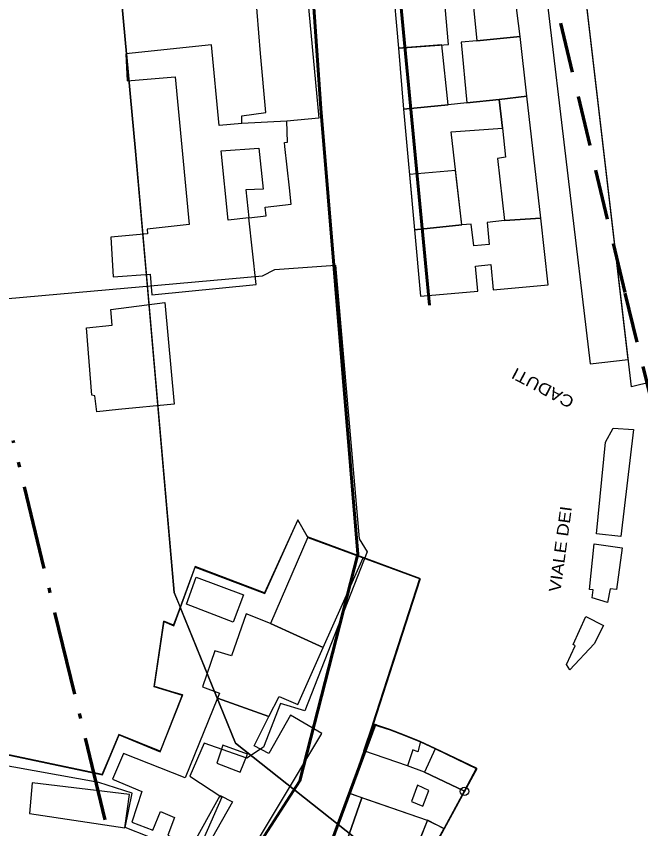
# Model space of a CAD drawing. Extents: x 654952 to 658955, y 890426 to 894481.
# Drawn here: x 658012.7 to 658161.5, y 891148.5 to 891342 of the extents above; entities that cross this region are included whole.
import ezdxf

# ---------------------------------------------------------------- set-up
doc = ezdxf.new("R2010")
doc.units = 0
doc.header["$LTSCALE"] = 4
doc.header["$PDMODE"] = 32
doc.header["$PDSIZE"] = 2
doc.linetypes.add('DOT_DASHED', pattern=[7.7, 5, -1.2, 0.3, -1.2])
doc.linetypes.add('MEDIUM_DASHED', pattern=[4.5, 3, -1.5])
for name, color, linetype, lineweight in [('1', 7, 'Continuous', 25), ('4', 7, 'Continuous', 25), ('40', 7, 'Continuous', 60), ('45', 7, 'Continuous', 25), ('55', 7, 'Continuous', 25), ('8', 7, 'Continuous', 25)]:
    doc.layers.add(name, color=color, linetype=linetype, lineweight=lineweight)
doc.layers.add('58', color=7, linetype='Continuous')

msp = doc.modelspace()

# ---------------------------------------------------------------- linework, layer by layer
at = {"layer": '1'}
for points in [[(658205.89, 891269.14), (658206.8, 891265.48), (658159.27, 891253.81), (658132.26, 891484.14), (658144.06, 891484.59)], [(658079.75, 891222.1), (658071.86, 891204.67), (658055.29, 891210.95), (658050.19, 891196.98), (658047.85, 891197.98), (658045.52, 891182.46)], [(658050.23, 891196.88), (658055.33, 891210.85), (658071.9, 891204.57), (658079.79, 891222), (658082.17, 891217.91), (658108.92, 891208.01)], [(658097.66, 891173.47), (658106.26, 891200.05), (658108.88, 891208.11), (658082.13, 891218.01), (658079.75, 891222.1)], [(658108.92, 891208.01), (658106.3, 891199.95), (658097.7, 891173.37), (658101.77, 891172.07), (658105.25, 891170.7), (658109.01, 891169.22), (658112.57, 891167.52), (658122.43, 891162.82), (658119.5, 891157.43)], [(658103.03, 891128.29), (658099.62, 891134.92), (658095.53, 891144.7), (658064.96, 891168.92), (658051.77, 891201.3), (658050.19, 891196.98), (658047.85, 891197.98), (658045.52, 891182.46)], [(658006.76, 891166.92), (658033.23, 891161.37), (658037.2, 891170.9), (658047.02, 891166.87), (658052.34, 891180.28), (658045.56, 891182.36), (658047.89, 891197.88), (658050.23, 891196.88)], [(658045.52, 891182.46), (658052.3, 891180.38), (658046.98, 891166.97), (658037.16, 891171), (658033.19, 891161.47), (658006.72, 891167.02), (658006.74, 891166.97), (658033.19, 891161.47), (658006.74, 891166.97)], [(658045.52, 891182.46), (658052.3, 891180.38), (658046.98, 891166.97), (658037.16, 891171), (658033.19, 891161.47), (658006.72, 891167.02), (658006.74, 891166.97)], [(658181.48, 891090.36), (658134.43, 891072.77), (658128.69, 891081.52), (658121.85, 891091.3), (658116.36, 891087.89), (658115.35, 891089.62), (658106.95, 891104.02), (658117.31, 891121.09), (658122.66, 891129.89), (658126.23, 891136.01), (658112.4, 891144.62), (658114.64, 891148.62), (658112.63, 891144.93), (658119.46, 891157.53), (658122.39, 891162.92), (658112.53, 891167.62), (658108.97, 891169.32), (658105.21, 891170.8), (658101.73, 891172.17), (658097.66, 891173.47)], [(658119.5, 891157.43), (658112.67, 891144.83), (658114.68, 891148.52), (658112.44, 891144.52), (658126.27, 891135.91), (658122.7, 891129.79), (658117.35, 891120.99), (658106.99, 891103.92), (658115.39, 891089.52), (658116.4, 891087.79), (658121.89, 891091.2), (658128.73, 891081.42), (658134.47, 891072.67), (658181.52, 891090.26), (658218.54, 891002.58), (658195.38, 890993.42), (658184.51, 891003.86), (658180.37, 891008.29), (658170.47, 891014.21), (658166.6, 891016.69), (658164.47, 891018.68), (658153.51, 891027.33), (658145.94, 891016.68), (658139.53, 891006.49)]]:
    msp.add_lwpolyline(points, dxfattribs=at)
msp.add_point((658119.5, 891157.43), dxfattribs=at)
at = {"layer": '4'}
for points in [[(658122.85, 891483.18), (658149.44, 891259.26), (658158.51, 891260.32), (658132.26, 891484.14)], [(658122.85, 891483.18), (658149.44, 891259.26), (658158.51, 891260.32), (658132.26, 891484.14)], [(658120.76, 891353.1), (658122.4, 891336.2), (658132.75, 891337.2), (658130.63, 891354.02)], [(658103.81, 891334.44), (658115.66, 891335.34), (658114.18, 891352.48), (658102.24, 891351.36)], [(658069.73, 891348), (658069.51, 891350.76), (658081.59, 891351.78), (658084.78, 891317.76), (658077.13, 891317.08), (658066.48, 891316.52), (658066.45, 891318.32), (658072.15, 891319.1), (658070.87, 891333.18)], [(658118.68, 891335.84), (658120.08, 891321.4), (658127.75, 891322.24), (658134.36, 891322.98), (658132.75, 891337.2), (658122.4, 891336.2)], [(658063.18, 891293.46), (658061.54, 891309.98), (658070.5, 891310.6), (658071.53, 891300.88), (658067.37, 891300.7), (658068.08, 891294), (658072.24, 891294.46), (658072.01, 891296.56), (658078.22, 891297.24), (658077.78, 891301.16), (658076.7, 891311), (658076.59, 891311.98), (658077.36, 891312.08), (658077.13, 891317.08), (658066.48, 891316.52), (658061.01, 891316.04), (658059.21, 891335.22), (658038.79, 891333.08), (658039.14, 891326.62), (658050.6, 891327.62), (658053.93, 891292.44), (658043.85, 891291.32), (658043.93, 891290.22), (658035.22, 891289.42), (658035.81, 891280), (658044.59, 891280.64), (658045.01, 891275.66), (658069.87, 891278.16), (658068.08, 891294)], [(658103.81, 891334.44), (658104.97, 891319.94), (658115.64, 891320.94), (658114.09, 891335.22)], [(658127.75, 891322.24), (658128.52, 891315.4), (658129.29, 891308.5), (658127.39, 891308.16), (658129.04, 891293.4), (658137.66, 891293.96), (658134.36, 891322.98)], [(658104.97, 891319.94), (658107.58, 891291.2), (658118.86, 891292.38), (658116.35, 891314.54), (658128.52, 891315.4), (658127.75, 891322.24), (658120.08, 891321.4), (658115.64, 891320.94)], [(658106.38, 891304.38), (658107.58, 891291.2), (658118.86, 891292.38), (658117.39, 891305.26)], [(658107.58, 891291.2), (658109.02, 891275.34), (658122.64, 891276.56), (658122.1, 891282.5), (658125.8, 891282.88), (658126.33, 891276.88), (658139.47, 891278.06), (658137.66, 891293.96), (658129.04, 891293.4), (658124.92, 891292.94), (658125.38, 891287.7), (658121.74, 891287.34), (658121.09, 891292.52), (658118.86, 891292.38)], [(658030.73, 891251.82), (658029.44, 891267.82), (658035.56, 891268.48), (658035.24, 891272.22), (658048.1, 891273.82), (658050.3, 891249.62), (658037.06, 891248.34), (658031.86, 891247.78), (658031.43, 891251.64)], [(658159.77, 891243.62), (658156.77, 891218.14), (658150.96, 891218.78), (658153.13, 891240.62), (658154.9, 891243.94)], [(658073.24, 891197.42), (658085.84, 891191.68), (658095.37, 891213.08), (658082.15, 891217.96)], [(658150.42, 891216.36), (658157.03, 891215.44), (658155.75, 891205.5), (658154.21, 891205.68), (658153.56, 891202.4), (658149.88, 891203.5), (658150.18, 891205.42), (658149.27, 891205.54)], [(658053.25, 891202), (658055.56, 891208.44), (658066.81, 891204.22), (658064.38, 891197.74)], [(658057.07, 891182.34), (658061.13, 891180.8), (658060.65, 891179.62), (658072.91, 891175.24), (658075.33, 891180.02), (658079.78, 891178.08), (658085.84, 891191.68), (658073.24, 891197.42), (658067.44, 891199.7), (658064.01, 891189.68), (658060, 891190.92)], [(658152.63, 891196.94), (658150.39, 891192.54), (658144.56, 891186.36), (658143.81, 891187.66), (658145.86, 891192.08), (658145.4, 891192.44), (658148.41, 891199.04)], [(658060.65, 891179.62), (658052.96, 891160.66), (658038.23, 891166.46), (658035.63, 891160.34), (658042.58, 891157.4), (658040.22, 891150.1), (658045.26, 891148.22), (658047.04, 891152.62), (658050.44, 891151.18), (658048.84, 891147), (658054.43, 891144.14), (658061.32, 891156.46), (658064.23, 891154.96), (658056.73, 891141.74), (658065.07, 891137.18), (658085.54, 891171.24), (658078.05, 891175.56), (658072.91, 891166.42), (658069.35, 891168.24), (658072.91, 891175.24)], [(658108.99, 891169.28), (658108.42, 891166.84), (658107.21, 891167.32), (658105.91, 891163.5), (658095.5, 891167.1), (658097.68, 891173.42), (658101.75, 891172.12)], [(658061.94, 891168.42), (658060.45, 891164.14), (658066.04, 891162), (658067.79, 891166.26)], [(658092.02, 891157.02), (658110.63, 891150.56), (658114.66, 891148.58), (658119.49, 891157.48), (658109.96, 891162.02), (658105.91, 891163.5), (658095.5, 891167.1)], [(658112.55, 891167.58), (658109.96, 891162.02), (658119.49, 891157.48), (658122.41, 891162.88)], [(658016.45, 891159.48), (658015.85, 891152.14), (658038.56, 891148.72), (658039.65, 891156.64)], [(658108.3, 891158.88), (658106.85, 891154.98), (658109.6, 891153.9), (658110.98, 891157.66)], [(658095.06, 891155.92), (658092.04, 891156.97), (658083.37, 891132.7), (658086.52, 891131.53)], [(658095.06, 891155.92), (658086.52, 891131.53), (658095.23, 891128.41), (658098, 891135.1), (658102.74, 891133.01), (658107.11, 891146.12), (658108.72, 891145.59), (658110.65, 891150.5)], [(658110.67, 891150.54), (658108.72, 891145.59), (658107.11, 891146.12), (658102.74, 891133.01), (658098, 891135.1), (658095.23, 891128.41), (658099.18, 891127), (658100.99, 891130.66), (658104, 891129.44), (658105.41, 891131.62), (658112.4, 891144.62), (658114.68, 891148.52)]]:
    msp.add_lwpolyline(points, close=True, dxfattribs=at)
at = {"layer": '40'}
for points in [[(658111.19, 891273.19), (658100.58, 891384.08), (658092.91, 891475.8), (658084.96, 891556.9), (658074.93, 891576.95), (658031.01, 891631.21)], [(658047.53, 891586.68), (658065.8, 891564.56), (658072.58, 891488.48), (658078.76, 891414.16), (658085.24, 891320.08), (658094.09, 891213.92), (658080.24, 891159.95), (658043.39, 891102.74), (658023.06, 891083.86), (658008.02, 891082.68)], [(658011.86, 891072.95), (658031.31, 891075.31), (658056.36, 891086.22), (658072.57, 891104.21), (658098.22, 891173.51)]]:
    msp.add_lwpolyline(points, dxfattribs=at)
at = {"layer": '45', "linetype": 'MEDIUM_DASHED', "lineweight": 70}
for points in [[(658157.77, 891276.21), (658107.08, 891488.64), (658089.9, 891548.82), (658084.95, 891562.68), (658066.38, 891640.44), (658054.95, 891687.7), (658032.46, 891785.55), (658025.97, 891822.86), (658018.45, 891880.89), (658014.38, 891931.66), (658013.11, 891975.37), (658014.47, 892047.73), (658020.79, 892120.53), (658030.81, 892187.14), (658035.6, 892213.52), (658095.39, 892463.77)], [(658467.75, 890621.37), (658447.66, 890651.14), (658324.04, 890835.2), (658279.74, 890902.58), (658248.15, 890956.2), (658220.13, 891019.53), (658157.73, 891276.4)]]:
    msp.add_lwpolyline(points, dxfattribs=at)
at = {"layer": '45', "linetype": 'DOT_DASHED', "lineweight": 70}
msp.add_lwpolyline([(658343.4, 890537.48), (658323.23, 890567.38), (658199.11, 890752.18), (658152.38, 890823.25), (658114.5, 890887.55), (658077.53, 890971.09), (658011.97, 891240.99)], dxfattribs=at)
at = {"layer": '55'}
for points in [[(658043.93, 891277.75), (658041.09, 891309.92), (658032.66, 891400.94), (658027.98, 891444.55), (658023.37, 891488.38), (658019.17, 891542.72), (658018.38, 891544.51), (658016.35, 891546.87), (658005.05, 891557.44), (657974.69, 891579.7), (657971.97, 891582.71)], [(657971.97, 891582.71), (657974.69, 891579.7), (658005.05, 891557.44), (658016.35, 891546.87), (658018.38, 891544.51), (658019.17, 891542.72), (658023.37, 891488.38), (658027.98, 891444.55), (658032.66, 891400.94), (658041.09, 891309.92), (658050.36, 891204.78), (658064.96, 891168.92), (658095.53, 891144.7), (658099.62, 891134.92), (658103.55, 891127.27), (658126.17, 891072.18), (658137.14, 891047.22), (658141.29, 891031.32), (658156.84, 890999.94), (658167.45, 891016.27)], [(657998.2, 891273.72), (657988.12, 891249.03), (657986.66, 891243.62), (657985.8, 891237.53), (657985.79, 891231.43), (657986.1, 891223.09), (657987.02, 891219.31), (657986.38, 891215.5), (657991.53, 891213.82), (657996.3, 891205.97), (657999.79, 891194.64), (658005.79, 891172.08), (658006.72, 891167.02), (658033.19, 891161.47), (658037.2, 891170.9), (658047.02, 891166.87), (658052.3, 891180.38), (658045.56, 891182.36), (658047.85, 891197.98), (658050.19, 891196.98), (658051.81, 891201.21), (658050.36, 891204.78), (658043.93, 891277.75)]]:
    msp.add_lwpolyline(points, dxfattribs=at)
at = {"layer": '8'}
msp.add_lwpolyline([(657998.2, 891273.72), (658071.4, 891280.17), (658074.3, 891281.7), (658088.79, 891282.73), (658094.42, 891217.56), (658096.29, 891214.49), (658081.46, 891176.62), (658075.67, 891178.33), (658071.57, 891167.92), (658067.65, 891165.36), (658057.49, 891168.91), (658054.08, 891161.06), (658061.65, 891156.08), (658055.55, 891142.16), (658038.67, 891148.81), (658040.33, 891157), (658032.36, 891159.56), (658007.19, 891164.08)], dxfattribs=at)

# ---------------------------------------------------------------- texts
at = {"layer": '58', "width": 1.15}
for s, rotation, p in [('CADUTI', 152.398, (658145.9, 891251.02)), ('VIALE DEI', 82.22, (658142.34, 891204.74))]:
    msp.add_text(s, height=2.799, rotation=rotation, dxfattribs=at).set_placement(p)

doc.saveas('drawing.dxf')
